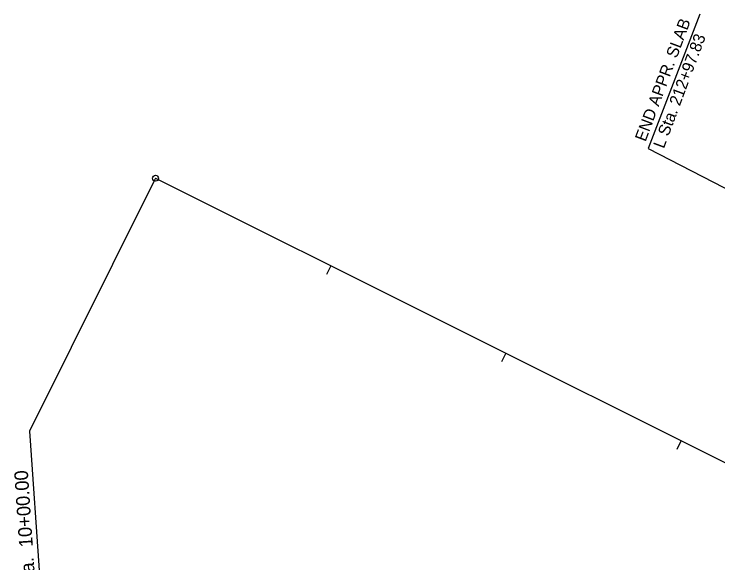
# Model space of a CAD drawing. Extents: x 2389694 to 2405615, y 547005 to 573532.
# Drawn here: x 2399738.7 to 2400098.2, y 568366.6 to 568646.7 of the extents above; entities that cross this region are included whole.
import ezdxf

# ---------------------------------------------------------------- set-up
doc = ezdxf.new("R2010")
doc.units = 0
for name, color, linetype in [('Prop Dimension', 7, 'Continuous'), ('Prop Dimension Text', 7, 'Continuous'), ('Prop Horizontal Alignment', 7, 'Continuous'), ('Prop Horizontal Alignment Curve and Spiral Data', 7, 'Continuous'), ('Prop Horizontal Alignment Tick Large', 7, 'Continuous'), ('Prop Horizontal Alignment Tick Small', 7, 'Continuous')]:
    doc.layers.add(name, color=color, linetype=linetype)

msp = doc.modelspace()

# ---------------------------------------------------------------- linework, layer by layer
at = {"layer": 'Prop Dimension'}
for p, q in [((2400089, 568646.66), (2400062.64, 568578)), ((2400062.64, 568578), (2400191.22, 568511.59))]:
    msp.add_line(p, q, dxfattribs=at)
at = {"layer": 'Prop Horizontal Alignment'}
msp.add_line((2399810.95, 568562.89), (2400526.85, 568205.84), dxfattribs=at)
at = {"layer": 'Prop Horizontal Alignment Curve and Spiral Data'}
for p, q in [((2399810.28, 568561.55), (2399746.58, 568433.83)), ((2399746.58, 568433.83), (2399754.78, 568316.68))]:
    msp.add_line(p, q, dxfattribs=at)
msp.add_circle((2399810.95, 568562.89), 1.5, dxfattribs=at)
at = {"layer": 'Prop Horizontal Alignment Tick Large'}
msp.add_line((2399810.95, 568562.89), (2399807.38, 568555.73), dxfattribs=at)
at = {"layer": 'Prop Horizontal Alignment Tick Small'}
for p, q in [((2399900.44, 568518.26), (2399898.21, 568513.79)), ((2399989.93, 568473.63), (2399987.7, 568469.16)), ((2400079.42, 568429), (2400077.18, 568424.52))]:
    msp.add_line(p, q, dxfattribs=at)

# ---------------------------------------------------------------- texts
at = {"layer": 'Prop Dimension Text'}
for s, p in [('END APPR. SLAB', (2400061.21, 568581.23)), ('L Sta. 212+97.83', (2400070.57, 568577.72))]:
    msp.add_text(s, height=6, rotation=69.473, dxfattribs=at).set_placement(p)
at = {"layer": 'Prop Horizontal Alignment Curve and Spiral Data'}
msp.add_text('-Y5- POT Sta.  10+00.00', height=7, rotation=93.8236, dxfattribs=at).set_placement((2399752.57, 568311.02))

doc.saveas('drawing.dxf')
